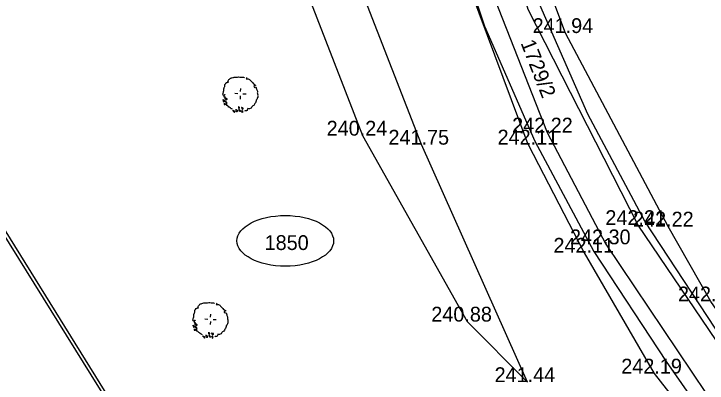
# Model space of a CAD drawing. Extents: x -601589 to -601440, y -1201842 to -1201527.
# Drawn here: x -601537.63 to -601490.84, y -1201664.93 to -1201639.98 of the extents above; entities that cross this region are included whole.
import ezdxf

# ---------------------------------------------------------------- set-up
doc = ezdxf.new("R2010")
doc.units = 0
for name, color, linetype in [('Definiční body', 7, 'Continuous'), ('Hranice parcel', 7, 'Continuous'), ('u_hrany', 7, 'Continuous'), ('u_vysadba', 7, 'Continuous'), ('u_vyska', 7, 'Continuous'), ('x_legenda', 7, 'Continuous')]:
    doc.layers.add(name, color=color, linetype=linetype)

msp = doc.modelspace()

# ---------------------------------------------------------------- linework, layer by layer
at = {"layer": 'Hranice parcel'}
for points in [[(-601518.5, -1201574.62), (-601510.22, -1201581.07), (-601510.94, -1201612.53), (-601510.72, -1201619.53), (-601510.05, -1201624.75), (-601508.24, -1201633.75), (-601505.86, -1201640.82), (-601502.47, -1201648.58), (-601498.5, -1201656.04), (-601493.62, -1201663.46), (-601488.75, -1201670.45), (-601479.72, -1201682.69), (-601461.88, -1201705.09), (-601445.87, -1201723.83)], [(-601445.87, -1201723.83), (-601456.99, -1201723.59), (-601475.22, -1201720.69), (-601492.39, -1201715.61), (-601519.73, -1201684.8), (-601540.64, -1201651.14), (-601563.05, -1201608.38), (-601567.44, -1201599.25)], [(-601460.43, -1201700.48), (-601476.54, -1201680.26), (-601485.5, -1201668.12), (-601490.31, -1201661.22), (-601495.06, -1201653.99), (-601498.9, -1201646.76), (-601502.13, -1201639.37), (-601504.35, -1201632.81), (-601505.66, -1201626.3)]]:
    msp.add_lwpolyline(points, dxfattribs=at)
at = {"layer": 'u_hrany'}
for points in [[(-601514.2, -1201569.51), (-601517.03, -1201570.93), (-601522.49, -1201584.67), (-601523.6, -1201596.8), (-601523.78, -1201607.28), (-601522.35, -1201622.38), (-601520.26, -1201632.29), (-601514.11, -1201648.21), (-601507.05, -1201660.77), (-601502.96, -1201664.86), (-601510.13, -1201648.82), (-601514.08, -1201638.6), (-601517, -1201627.14), (-601517.98, -1201618.06), (-601518.55, -1201594.5), (-601514.93, -1201583.59), (-601509.76, -1201580.82)], [(-601567.51, -1201596.21), (-601562.55, -1201607.8), (-601549.33, -1201634.79), (-601540.29, -1201651.32), (-601519.62, -1201684.67)], [(-601460.33, -1201700.35), (-601477.02, -1201679.01), (-601490.59, -1201659.41), (-601493.47, -1201654.35), (-601500.4, -1201641.28), (-601502.56, -1201635.52), (-601504.77, -1201626.02), (-601500.77, -1201618.77)], [(-601443.32, -1201721.42), (-601460.41, -1201701.5), (-601476.94, -1201680.56), (-601485.91, -1201668.41), (-601495.49, -1201654.25), (-601502.92, -1201639.69), (-601504.84, -1201632.93)], [(-601502.92, -1201648.81), (-601508.49, -1201633.89)], [(-601507.17, -1201633.88), (-601501.63, -1201648), (-601497.69, -1201655.55), (-601488, -1201669.96), (-601478.86, -1201682.08), (-601462.72, -1201703.16), (-601444.89, -1201723.91)], [(-601502.92, -1201648.81), (-601499.15, -1201656.12), (-601494.42, -1201664.28), (-601479.96, -1201682.77)]]:
    msp.add_lwpolyline(points, dxfattribs=at)
at = {"layer": 'u_vysadba'}
for points in [[(-601523.335, -1201644.685), (-601523.333, -1201644.656), (-601523.273, -1201644.63), (-601523.243, -1201644.617), (-601523.213, -1201644.604), (-601523.184, -1201644.605), (-601523.155, -1201644.607), (-601523.168, -1201644.577), (-601523.181, -1201644.547), (-601523.164, -1201644.504), (-601523.147, -1201644.461), (-601523.116, -1201644.418), (-601523.085, -1201644.391), (-601523.054, -1201644.363), (-601523.009, -1201644.336), (-601522.965, -1201644.338), (-601522.934, -1201644.311), (-601522.86, -1201644.285), (-601522.801, -1201644.274), (-601522.756, -1201644.262), (-601522.698, -1201644.265), (-601522.653, -1201644.252), (-601522.609, -1201644.255), (-601522.536, -1201644.259), (-601522.463, -1201644.248), (-601522.39, -1201644.252), (-601522.302, -1201644.256), (-601522.214, -1201644.261), (-601522.141, -1201644.265), (-601522.098, -1201644.282), (-601522.07, -1201644.298)], [(-601521.923, -1201644.291), (-601521.939, -1201644.319), (-601521.941, -1201644.349), (-601521.957, -1201644.377), (-601521.912, -1201644.365), (-601521.883, -1201644.366), (-601521.854, -1201644.368), (-601521.811, -1201644.385), (-601521.767, -1201644.387), (-601521.725, -1201644.419), (-601521.697, -1201644.449), (-601521.67, -1201644.495), (-601521.628, -1201644.526), (-601521.572, -1201644.573), (-601521.53, -1201644.619), (-601521.503, -1201644.65), (-601521.462, -1201644.711), (-601521.405, -1201644.743), (-601521.363, -1201644.775), (-601521.32, -1201644.791), (-601521.321, -1201644.821)], [(-601523.335, -1201644.685), (-601523.336, -1201644.7), (-601523.382, -1201644.741), (-601523.413, -1201644.769), (-601523.415, -1201644.813), (-601523.417, -1201644.856), (-601523.42, -1201644.915), (-601523.437, -1201644.958), (-601523.453, -1201644.986), (-601523.469, -1201645.015), (-601523.487, -1201645.072), (-601523.489, -1201645.102), (-601523.492, -1201645.16), (-601523.494, -1201645.204), (-601523.496, -1201645.233), (-601523.514, -1201645.305), (-601523.531, -1201645.348), (-601523.533, -1201645.392), (-601523.549, -1201645.42), (-601523.536, -1201645.45), (-601523.493, -1201645.467), (-601523.404, -1201645.443), (-601523.374, -1201645.43), (-601523.407, -1201645.487), (-601523.437, -1201645.514), (-601523.453, -1201645.543), (-601523.456, -1201645.586), (-601523.427, -1201645.588), (-601523.383, -1201645.59), (-601523.37, -1201645.62), (-601523.387, -1201645.663), (-601523.403, -1201645.692), (-601523.405, -1201645.736), (-601523.407, -1201645.779)], [(-601521.321, -1201644.821), (-601521.366, -1201644.833), (-601521.411, -1201644.845), (-601521.427, -1201644.874), (-601521.414, -1201644.904), (-601521.387, -1201644.949), (-601521.357, -1201644.936), (-601521.312, -1201644.924), (-601521.284, -1201644.954), (-601521.271, -1201644.984), (-601521.273, -1201645.014), (-601521.247, -1201645.074), (-601521.235, -1201645.118), (-601521.222, -1201645.163), (-601521.195, -1201645.208), (-601521.197, -1201645.237), (-601521.199, -1201645.281), (-601521.201, -1201645.31), (-601521.189, -1201645.355), (-601521.177, -1201645.414), (-601521.18, -1201645.472), (-601521.169, -1201645.532), (-601521.17, -1201645.561), (-601521.172, -1201645.59), (-601521.174, -1201645.634), (-601521.205, -1201645.661), (-601521.206, -1201645.691), (-601521.223, -1201645.734), (-601521.239, -1201645.762), (-601521.285, -1201645.804), (-601521.289, -1201645.862), (-601521.306, -1201645.92), (-601521.325, -1201645.992), (-601521.372, -1201646.048), (-601521.405, -1201646.119), (-601521.437, -1201646.176), (-601521.497, -1201646.202), (-601521.528, -1201646.23), (-601521.574, -1201646.272), (-601521.605, -1201646.314), (-601521.622, -1201646.357), (-601521.682, -1201646.383), (-601521.727, -1201646.395), (-601521.757, -1201646.408), (-601521.8, -1201646.391), (-601521.843, -1201646.375), (-601521.86, -1201646.418), (-601521.877, -1201646.475), (-601521.894, -1201646.518), (-601521.939, -1201646.531), (-601521.983, -1201646.528)], [(-601522.519, -1201645.378), (-601522.724, -1201645.367)], [(-601522.335, -1201645.227), (-601522.325, -1201645.022)], [(-601522.169, -1201645.396), (-601521.963, -1201645.393)], [(-601523.539, -1201645.772), (-601523.526, -1201645.802), (-601523.513, -1201645.847), (-601523.5, -1201645.877), (-601523.502, -1201645.906), (-601523.473, -1201645.922), (-601523.443, -1201645.895), (-601523.397, -1201645.853), (-601523.426, -1201645.852), (-601523.468, -1201645.82), (-601523.511, -1201645.803)], [(-601523.381, -1201645.839), (-601523.34, -1201645.885), (-601523.298, -1201645.932), (-601523.256, -1201645.963)], [(-601523.256, -1201645.963), (-601523.285, -1201645.962), (-601523.314, -1201645.96), (-601523.344, -1201645.958), (-601523.357, -1201645.929), (-601523.355, -1201645.899), (-601523.368, -1201645.869)], [(-601523.357, -1201645.65), (-601523.359, -1201645.694), (-601523.346, -1201645.724), (-601523.334, -1201645.769), (-601523.32, -1201645.799), (-601523.291, -1201645.8), (-601523.275, -1201645.772), (-601523.215, -1201645.746), (-601523.258, -1201645.729), (-601523.287, -1201645.713), (-601523.344, -1201645.68)], [(-601522.352, -1201645.533), (-601522.362, -1201645.738)], [(-601523.449, -1201646.011), (-601523.439, -1201646.1), (-601523.395, -1201646.102), (-601523.366, -1201646.104), (-601523.321, -1201646.091), (-601523.379, -1201646.074), (-601523.423, -1201646.071), (-601523.436, -1201646.041)], [(-601522.885, -1201646.422), (-601522.928, -1201646.405), (-601522.956, -1201646.389), (-601522.986, -1201646.387), (-601523.012, -1201646.342), (-601523.041, -1201646.326), (-601523.083, -1201646.294), (-601523.126, -1201646.277), (-601523.168, -1201646.231), (-601523.195, -1201646.201), (-601523.267, -1201646.168), (-601523.264, -1201646.124), (-601523.262, -1201646.08), (-601523.275, -1201646.05), (-601523.304, -1201646.034), (-601523.272, -1201645.992), (-601523.243, -1201645.993)], [(-601522.481, -1201646.253), (-601522.47, -1201646.327), (-601522.443, -1201646.372), (-601522.398, -1201646.36), (-601522.397, -1201646.331), (-601522.395, -1201646.301), (-601522.438, -1201646.285), (-601522.467, -1201646.268)], [(-601522.278, -1201646.293), (-601522.252, -1201646.353), (-601522.239, -1201646.398), (-601522.212, -1201646.428), (-601522.182, -1201646.415), (-601522.15, -1201646.373), (-601522.149, -1201646.344), (-601522.192, -1201646.341), (-601522.221, -1201646.325), (-601522.249, -1201646.309), (-601522.278, -1201646.308)], [(-601522.873, -1201646.481), (-601522.777, -1201646.603), (-601522.75, -1201646.649), (-601522.719, -1201646.606), (-601522.717, -1201646.577), (-601522.746, -1201646.561), (-601522.789, -1201646.544), (-601522.817, -1201646.528), (-601522.846, -1201646.512)], [(-601522.651, -1201646.434), (-601522.655, -1201646.507), (-601522.643, -1201646.552), (-601522.615, -1201646.583), (-601522.556, -1201646.571), (-601522.525, -1201646.543), (-601522.538, -1201646.514), (-601522.581, -1201646.497), (-601522.624, -1201646.48)], [(-601522.446, -1201646.431), (-601522.362, -1201646.508), (-601522.334, -1201646.524), (-601522.321, -1201646.554), (-601522.352, -1201646.582), (-601522.381, -1201646.58), (-601522.394, -1201646.55), (-601522.421, -1201646.505), (-601522.448, -1201646.474)], [(-601522.247, -1201646.544), (-601522.236, -1201646.617), (-601522.223, -1201646.647), (-601522.193, -1201646.634), (-601522.162, -1201646.592), (-601522.189, -1201646.561), (-601522.218, -1201646.545), (-601522.247, -1201646.544)], [(-601521.983, -1201646.528), (-601522.027, -1201646.541), (-601522.058, -1201646.568)], [(-601525.353, -1201659.926), (-601525.354, -1201659.941), (-601525.4, -1201659.983), (-601525.431, -1201660.01), (-601525.433, -1201660.054), (-601525.435, -1201660.098), (-601525.439, -1201660.156), (-601525.455, -1201660.199), (-601525.472, -1201660.228), (-601525.488, -1201660.256), (-601525.505, -1201660.314), (-601525.507, -1201660.343), (-601525.51, -1201660.401), (-601525.512, -1201660.445), (-601525.514, -1201660.474), (-601525.532, -1201660.547), (-601525.549, -1201660.59), (-601525.552, -1201660.633), (-601525.568, -1201660.662), (-601525.555, -1201660.692), (-601525.512, -1201660.709), (-601525.422, -1201660.684), (-601525.393, -1201660.671), (-601525.425, -1201660.728), (-601525.456, -1201660.756), (-601525.472, -1201660.784), (-601525.474, -1201660.828), (-601525.445, -1201660.829), (-601525.401, -1201660.832), (-601525.388, -1201660.862), (-601525.405, -1201660.905), (-601525.421, -1201660.933), (-601525.423, -1201660.977), (-601525.426, -1201661.021)], [(-601525.353, -1201659.926), (-601525.352, -1201659.897), (-601525.292, -1201659.871), (-601525.262, -1201659.858), (-601525.232, -1201659.845), (-601525.203, -1201659.847), (-601525.173, -1201659.848), (-601525.186, -1201659.818), (-601525.199, -1201659.788), (-601525.183, -1201659.745), (-601525.166, -1201659.702), (-601525.134, -1201659.66), (-601525.103, -1201659.632), (-601525.073, -1201659.605), (-601525.027, -1201659.578), (-601524.983, -1201659.58), (-601524.953, -1201659.552), (-601524.878, -1201659.527), (-601524.819, -1201659.515), (-601524.774, -1201659.503), (-601524.716, -1201659.506), (-601524.671, -1201659.494), (-601524.628, -1201659.496), (-601524.555, -1201659.5), (-601524.481, -1201659.489), (-601524.408, -1201659.493), (-601524.32, -1201659.498), (-601524.233, -1201659.502), (-601524.16, -1201659.506), (-601524.117, -1201659.523), (-601524.088, -1201659.539)], [(-601523.941, -1201659.532), (-601523.957, -1201659.561), (-601523.959, -1201659.59), (-601523.975, -1201659.619), (-601523.931, -1201659.606), (-601523.901, -1201659.608), (-601523.872, -1201659.609), (-601523.829, -1201659.626), (-601523.785, -1201659.629), (-601523.743, -1201659.66), (-601523.715, -1201659.691), (-601523.688, -1201659.736), (-601523.646, -1201659.768), (-601523.59, -1201659.815), (-601523.549, -1201659.861), (-601523.521, -1201659.891), (-601523.48, -1201659.952), (-601523.423, -1201659.984), (-601523.381, -1201660.016), (-601523.338, -1201660.033), (-601523.34, -1201660.062)], [(-601524.354, -1201660.468), (-601524.343, -1201660.264)], [(-601523.34, -1201660.062), (-601523.384, -1201660.074), (-601523.429, -1201660.087), (-601523.445, -1201660.115), (-601523.432, -1201660.145), (-601523.405, -1201660.19), (-601523.375, -1201660.177), (-601523.33, -1201660.165), (-601523.303, -1201660.196), (-601523.29, -1201660.226), (-601523.291, -1201660.255), (-601523.265, -1201660.315), (-601523.253, -1201660.36), (-601523.241, -1201660.404), (-601523.214, -1201660.449), (-601523.215, -1201660.479), (-601523.218, -1201660.522), (-601523.219, -1201660.552), (-601523.207, -1201660.596), (-601523.195, -1201660.655), (-601523.198, -1201660.714), (-601523.187, -1201660.773), (-601523.188, -1201660.802), (-601523.19, -1201660.831), (-601523.192, -1201660.875), (-601523.223, -1201660.903), (-601523.225, -1201660.932), (-601523.241, -1201660.975), (-601523.258, -1201661.004), (-601523.304, -1201661.045), (-601523.307, -1201661.103), (-601523.324, -1201661.161), (-601523.343, -1201661.233), (-601523.39, -1201661.289), (-601523.423, -1201661.361), (-601523.455, -1201661.418), (-601523.515, -1201661.444), (-601523.546, -1201661.472), (-601523.592, -1201661.513), (-601523.624, -1201661.555), (-601523.64, -1201661.598), (-601523.7, -1201661.624), (-601523.745, -1201661.637), (-601523.775, -1201661.65), (-601523.818, -1201661.633), (-601523.861, -1201661.616), (-601523.878, -1201661.659), (-601523.896, -1201661.717), (-601523.913, -1201661.76), (-601523.957, -1201661.772), (-601524.001, -1201661.77)], [(-601525.375, -1201660.892), (-601525.377, -1201660.936), (-601525.364, -1201660.966), (-601525.352, -1201661.01), (-601525.339, -1201661.04), (-601525.31, -1201661.042), (-601525.293, -1201661.013), (-601525.233, -1201660.987), (-601525.277, -1201660.97), (-601525.305, -1201660.954), (-601525.362, -1201660.922)], [(-601524.537, -1201660.619), (-601524.742, -1201660.609)], [(-601524.37, -1201660.775), (-601524.381, -1201660.979)], [(-601524.187, -1201660.638), (-601523.982, -1201660.634)], [(-601525.557, -1201661.014), (-601525.544, -1201661.044), (-601525.532, -1201661.088), (-601525.519, -1201661.118), (-601525.52, -1201661.148), (-601525.492, -1201661.164), (-601525.461, -1201661.136), (-601525.415, -1201661.095), (-601525.444, -1201661.093), (-601525.486, -1201661.062), (-601525.529, -1201661.045)], [(-601525.467, -1201661.253), (-601525.457, -1201661.341), (-601525.413, -1201661.344), (-601525.384, -1201661.345), (-601525.34, -1201661.333), (-601525.397, -1201661.315), (-601525.441, -1201661.313), (-601525.454, -1201661.283)], [(-601525.4, -1201661.081), (-601525.358, -1201661.127), (-601525.317, -1201661.173), (-601525.274, -1201661.205)], [(-601525.274, -1201661.205), (-601525.303, -1201661.203), (-601525.333, -1201661.201), (-601525.362, -1201661.2), (-601525.375, -1201661.17), (-601525.373, -1201661.141), (-601525.386, -1201661.111)], [(-601524.903, -1201661.663), (-601524.946, -1201661.647), (-601524.975, -1201661.63), (-601525.004, -1201661.629), (-601525.031, -1201661.583), (-601525.059, -1201661.567), (-601525.101, -1201661.536), (-601525.144, -1201661.519), (-601525.186, -1201661.473), (-601525.214, -1201661.442), (-601525.285, -1201661.409), (-601525.283, -1201661.365), (-601525.28, -1201661.321), (-601525.293, -1201661.291), (-601525.322, -1201661.275), (-601525.29, -1201661.233), (-601525.261, -1201661.235)], [(-601524.892, -1201661.723), (-601524.796, -1201661.845), (-601524.769, -1201661.89), (-601524.737, -1201661.848), (-601524.736, -1201661.819), (-601524.764, -1201661.803), (-601524.807, -1201661.786), (-601524.836, -1201661.769), (-601524.864, -1201661.753)], [(-601524.67, -1201661.676), (-601524.673, -1201661.749), (-601524.661, -1201661.793), (-601524.633, -1201661.824), (-601524.574, -1201661.813), (-601524.544, -1201661.785), (-601524.557, -1201661.755), (-601524.6, -1201661.738), (-601524.643, -1201661.721)], [(-601524.499, -1201661.494), (-601524.488, -1201661.568), (-601524.461, -1201661.614), (-601524.417, -1201661.601), (-601524.415, -1201661.572), (-601524.414, -1201661.543), (-601524.457, -1201661.526), (-601524.485, -1201661.51)], [(-601524.464, -1201661.672), (-601524.381, -1201661.75), (-601524.352, -1201661.766), (-601524.339, -1201661.796), (-601524.37, -1201661.823), (-601524.399, -1201661.822), (-601524.412, -1201661.792), (-601524.439, -1201661.747), (-601524.467, -1201661.716)], [(-601524.296, -1201661.534), (-601524.27, -1201661.594), (-601524.258, -1201661.639), (-601524.23, -1201661.67), (-601524.2, -1201661.657), (-601524.168, -1201661.614), (-601524.167, -1201661.585), (-601524.211, -1201661.583), (-601524.239, -1201661.567), (-601524.268, -1201661.551), (-601524.297, -1201661.549)], [(-601524.265, -1201661.785), (-601524.255, -1201661.859), (-601524.241, -1201661.889), (-601524.212, -1201661.876), (-601524.18, -1201661.833), (-601524.208, -1201661.803), (-601524.236, -1201661.787), (-601524.265, -1201661.785)], [(-601524.001, -1201661.77), (-601524.046, -1201661.782), (-601524.076, -1201661.81)]]:
    msp.add_lwpolyline(points, dxfattribs=at)
at = {"layer": 'x_legenda'}
msp.add_ellipse((-601519.313, -1201655.318), major_axis=(3.261, 0), ratio=0.524694, dxfattribs=at)

# ---------------------------------------------------------------- texts
at = {"layer": 'Definiční body'}
msp.add_text('1729/2', height=1, rotation=291.4226, dxfattribs=at).set_placement((-601503.447, -1201641.951))
msp.add_text('1850', height=1, dxfattribs=at).set_placement((-601520.71, -1201655.936))
at = {"layer": 'u_vyska'}
for s, p in [('241.94', (-601502.623, -1201641.28)), ('240.24', (-601516.523, -1201648.21)), ('242.22', (-601504.004, -1201648)), ('241.75', (-601512.351, -1201648.82)), ('242.11', (-601504.987, -1201648.81)), ('242.21', (-601497.712, -1201654.25)), ('242.22', (-601495.844, -1201654.35)), ('242.30', (-601500.099, -1201655.55)), ('242.11', (-601501.217, -1201656.12)), ('242.14', (-601492.814, -1201659.41)), ('240.88', (-601509.459, -1201660.77)), ('242.19', (-601496.639, -1201664.28)), ('241.44', (-601505.188, -1201664.86))]:
    msp.add_text(s, height=1, dxfattribs=at).set_placement(p)

doc.saveas('drawing.dxf')
